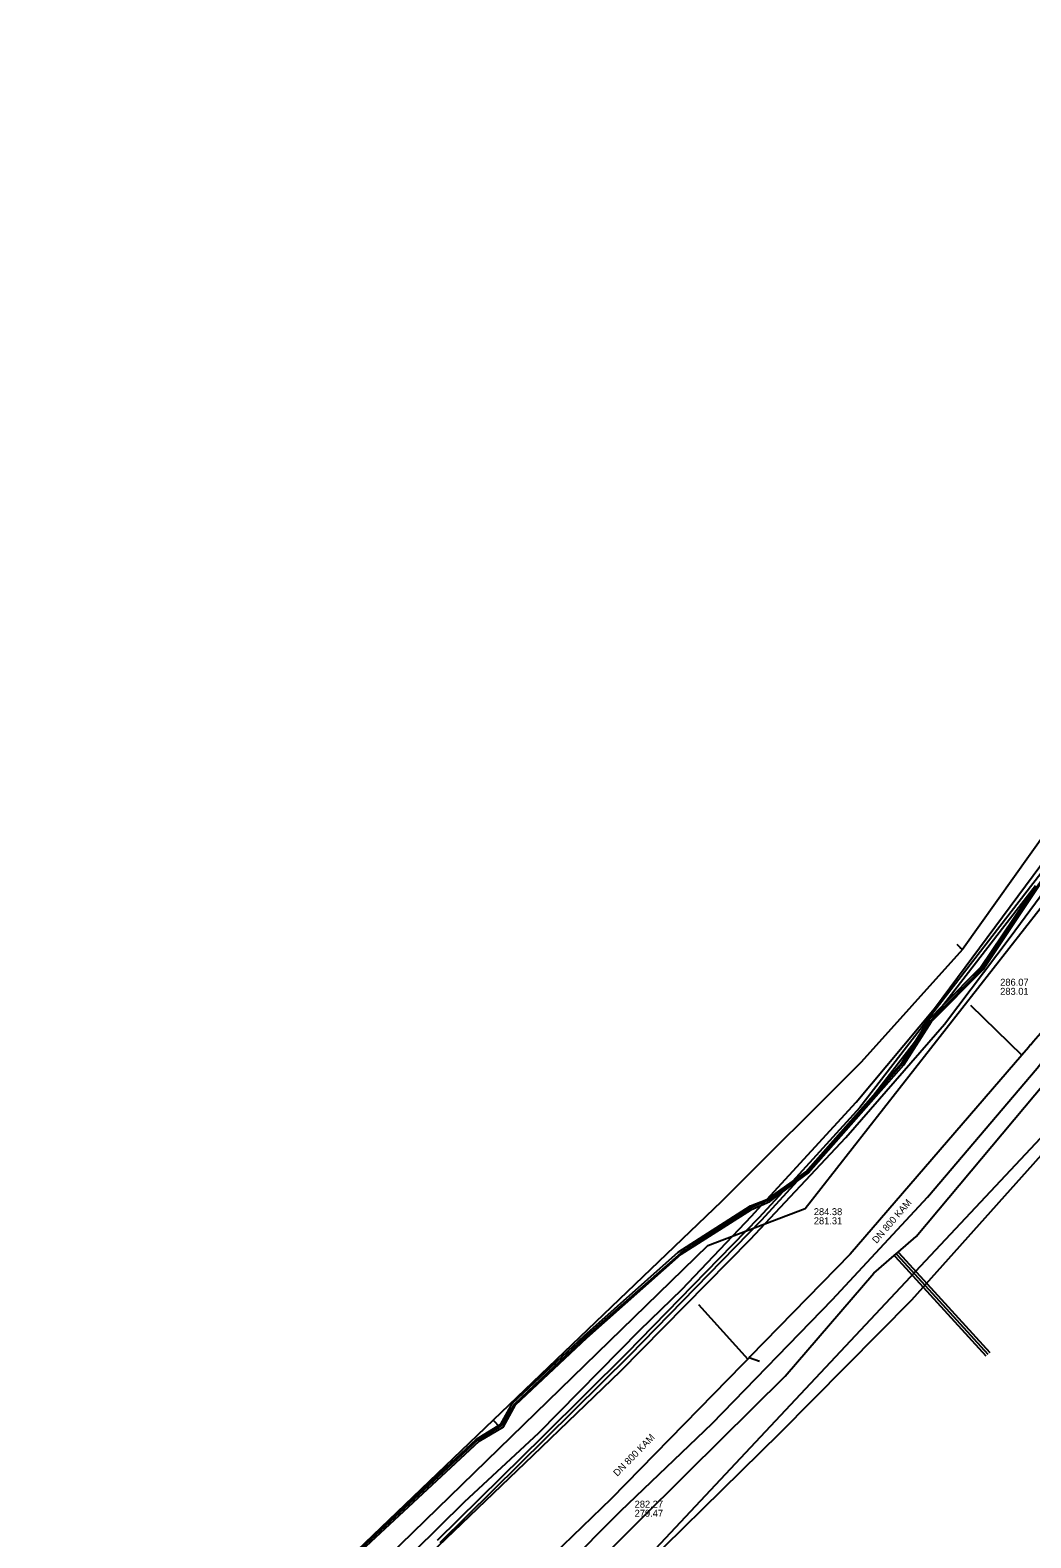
# Model space of a CAD drawing. Extents: x -598233 to -596890, y -1157848 to -1156431.
# Drawn here: x -597113.1 to -596997.9, y -1156997.4 to -1156824 of the extents above; entities that cross this region are included whole.
import ezdxf

# ---------------------------------------------------------------- set-up
doc = ezdxf.new("R2010")
doc.units = 0
for name, color, linetype in [('Vrstva 12', 7, 'Continuous'), ('Vrstva 13', 7, 'Continuous'), ('Vrstva 19', 7, 'Continuous'), ('Vrstva 44', 7, 'Continuous'), ('Vrstva 55', 7, 'Continuous'), ('Vrstva 58', 7, 'Continuous'), ('Vrstva 9', 7, 'Continuous')]:
    doc.layers.add(name, color=color, linetype=linetype)

msp = doc.modelspace()

# ---------------------------------------------------------------- linework, layer by layer
at = {"layer": 'Vrstva 12'}
for points in [[(-597013.15, -1156964.56), (-597011.08, -1156962.78), (-596994.85, -1156943.41)], [(-597096.15, -1157046.37), (-597080.65, -1157032.41), (-597068.22, -1157020.09), (-597055.1, -1157007.53), (-597037.34, -1156989.94), (-597026.15, -1156978.85), (-597015.97, -1156966.98), (-597013.61, -1156964.95)], [(-597013.61, -1156964.95), (-597013.38, -1156964.76)], [(-597013.38, -1156964.76), (-597013.15, -1156964.56)], [(-597002.58, -1156976.15), (-597008.97, -1156969.14), (-597013.02, -1156964.71), (-597013.15, -1156964.56)]]:
    msp.add_lwpolyline(points, dxfattribs=at)
at = {"layer": 'Vrstva 13'}
for p, q in [((-597006, -1156929.52), (-597006.36, -1156929.2)), ((-597005.76, -1156929.74), (-597006, -1156929.52)), ((-597059.77, -1156983.91), (-597059.54, -1156984.14)), ((-597059.54, -1156984.14), (-597059.21, -1156984.48))]:
    msp.add_line(p, q, dxfattribs=at)
for points in [[(-596967.78, -1156864.53), (-596968.28, -1156866.45), (-596969.12, -1156869.63), (-596975.82, -1156881.68), (-596987.36, -1156902), (-596995.97, -1156916.01), (-597005.76, -1156929.74), (-597017.4, -1156942.73), (-597033.49, -1156958.74), (-597059.77, -1156983.91), (-597076.36, -1156999.81), (-597090.23, -1157012.97), (-597109.08, -1157030.59), (-597111.35, -1157034.13), (-597112.48, -1157035.47), (-597112.98, -1157036.09)], [(-597003.02, -1156976.55), (-597009.42, -1156969.53), (-597013.47, -1156965.1), (-597013.61, -1156964.95)], [(-597002.8, -1156976.35), (-597009.2, -1156969.34), (-597013.24, -1156964.91), (-597013.38, -1156964.76)]]:
    msp.add_lwpolyline(points, dxfattribs=at)
at = {"layer": 'Vrstva 19'}
msp.add_lwpolyline([(-597070.67, -1157028.24), (-597069.06, -1157026.66), (-597068.04, -1157025.67), (-597047.41, -1157005.47), (-596990.41, -1156944.69), (-596980.1, -1156930.5), (-596969.41, -1156912.52), (-596962.33, -1156901.94), (-596955.88, -1156890.47), (-596948.03, -1156875.88), (-596944.82, -1156870.73), (-596944.5, -1156869.71)], dxfattribs=at)
at = {"layer": 'Vrstva 44'}
for points in [[(-597074.66, -1157004.75), (-597063.06, -1156993.3), (-597054.52, -1156985.37), (-597042.87, -1156973.56), (-597038.02, -1156968.83), (-597030.03, -1156960.43), (-597028.88, -1156959.17), (-597028.54, -1156958.8), (-597028.27, -1156958.51), (-597018, -1156947.32), (-597008.96, -1156936.55), (-596993.33, -1156915.45), (-596979.36, -1156891.26), (-596973.04, -1156878.64), (-596966.53, -1156865.27), (-596961.1, -1156853.21), (-596958.95, -1156848.68), (-596955.64, -1156843.49), (-596947.56, -1156826.18), (-596941.41, -1156813.85)], [(-596993.84, -1156917.29), (-597017.56, -1156947.92), (-597025.33, -1156956.43), (-597025.84, -1156956.99), (-597026.44, -1156957.64), (-597029.17, -1156960.64), (-597044.38, -1156976.19), (-597054.02, -1156985.75), (-597066.19, -1156997.75)], [(-597076.54, -1157000.38), (-597061.39, -1156986.32), (-597058.58, -1156984.67), (-597057.18, -1156982.13), (-597048.99, -1156974.43), (-597038.12, -1156964.8), (-597030.02, -1156959.68), (-597028.88, -1156959.17), (-597027.93, -1156958.74), (-597026.44, -1156957.64), (-597024.78, -1156956.42), (-597023.48, -1156955.47), (-597012.51, -1156943.03), (-597009.32, -1156938.03), (-597003.37, -1156932.06), (-596994.69, -1156919.04)], [(-596995.59, -1156920.2), (-597003.51, -1156931.93), (-597009.05, -1156937.58), (-597009.45, -1156937.99), (-597009.9, -1156938.68), (-597012.64, -1156942.89), (-597017.02, -1156947.88), (-597018.09, -1156949.09), (-597023.61, -1156955.38), (-597024.25, -1156955.84), (-597025.84, -1156956.99), (-597028.05, -1156958.58), (-597028.54, -1156958.8), (-597030.07, -1156959.49), (-597038.16, -1156964.69), (-597049.11, -1156974.3), (-597057.32, -1156982.05), (-597058.79, -1156984.53), (-597061.56, -1156986.22), (-597076.71, -1157000.33)], [(-597076.79, -1157000.19), (-597061.68, -1156986.08), (-597058.89, -1156984.38), (-597057.54, -1156981.94), (-597049.3, -1156974.21), (-597038.49, -1156964.57), (-597030.13, -1156959.25), (-597028.27, -1156958.51), (-597028.18, -1156958.47), (-597025.33, -1156956.43), (-597023.78, -1156955.32), (-597015.71, -1156946.19), (-597012.73, -1156942.81), (-597011.14, -1156940.29), (-597009.59, -1156937.81), (-597007.93, -1156936.13), (-597003.68, -1156931.84), (-596997.33, -1156922.45)], [(-596997.33, -1156922.45), (-597007.93, -1156936.13), (-597009.05, -1156937.58), (-597009.9, -1156938.68), (-597011.14, -1156940.29), (-597015.71, -1156946.19), (-597017.02, -1156947.88), (-597017.26, -1156948.18), (-597018.09, -1156949.09), (-597024.25, -1156955.84), (-597024.78, -1156956.42), (-597028.88, -1156960.91), (-597044.09, -1156976.48), (-597053.74, -1156986.03), (-597065.91, -1156998.03)]]:
    msp.add_lwpolyline(points, dxfattribs=at)
at = {"layer": 'Vrstva 55'}
for points in [[(-597069.74, -1157001.91), (-597055.17, -1156987.92), (-597045.1, -1156978.26), (-597030.18, -1156963.14), (-597019.16, -1156951.4), (-597007.83, -1156938.34), (-597000.27, -1156928.35), (-596991.63, -1156916.64), (-596988.25, -1156910.28), (-596981.73, -1156899.08), (-596978.12, -1156892.58), (-596971.83, -1156880.35), (-596964.21, -1156865.06), (-596948.88, -1156874.21), (-596946.12, -1156870.53), (-596945.7, -1156867.33), (-596942.11, -1156860.7), (-596931.98, -1156866.05), (-596927.82, -1156861.81), (-596924.03, -1156860.35)], [(-597058.24, -1157007.55), (-597045.07, -1156994.34), (-597034.55, -1156984.29), (-597020.7, -1156970.03), (-597009.79, -1156958.24), (-596997.15, -1156943.42), (-596987.85, -1156931.37), (-596977.1, -1156914.45), (-596969.49, -1156901.48), (-596959.56, -1156881.26), (-596954.35, -1156871.52), (-596948.75, -1156874.87)]]:
    msp.add_lwpolyline(points, dxfattribs=at)
at = {"layer": 'Vrstva 58'}
for points in [[(-597115.64, -1157042.19), (-597035.06, -1156963.83), (-597023.86, -1156959.57), (-596991.41, -1156918.15), (-596951.34, -1156839.56), (-596924.93, -1156788.51), (-596911.05, -1156767.47), (-596898.61, -1156749.4), (-596890.46, -1156742.24)], [(-597086.88, -1157045.18), (-597086.58, -1157044.59), (-597066.89, -1157025.23), (-597051.01, -1157009.31), (-597046.7, -1157005.01), (-597026.73, -1156985.36), (-597011.58, -1156970.08), (-596991.8, -1156947.93), (-596989.15, -1156945.07), (-596988.35, -1156943.93), (-596988.21, -1156942.76), (-596974.88, -1156923.46), (-596956.71, -1156889.88), (-596946.89, -1156871.03), (-596942.11, -1156860.2), (-596941.85, -1156859.79), (-596941.53, -1156859.01), (-596934.53, -1156842.22), (-596932.96, -1156839.31), (-596920.95, -1156815.01), (-596913.39, -1156801.07), (-596903.8, -1156786.32), (-596893.16, -1156776.74), (-596890.46, -1156773.58)]]:
    msp.add_lwpolyline(points, dxfattribs=at)
at = {"layer": 'Vrstva 9'}
for p, q in [((-597004.83, -1156936.18), (-596998.92, -1156941.9)), ((-597036.12, -1156970.59), (-597030.46, -1156976.87)), ((-597029.12, -1156977.14), (-597030.31, -1156976.72))]:
    msp.add_line(p, q, dxfattribs=at)
for points in [[(-596995.7, -1156938.18), (-596997.56, -1156940.33), (-596997.9, -1156940.72), (-596997.95, -1156940.78), (-596998.06, -1156940.91), (-596998.16, -1156941.03), (-596998.92, -1156941.9), (-597018.67, -1156964.82)], [(-597018.67, -1156964.82), (-597030.17, -1156976.57), (-597030.21, -1156976.62), (-597030.31, -1156976.72), (-597030.46, -1156976.87), (-597031.04, -1156977.46), (-597031.07, -1156977.5), (-597046.19, -1156992.95)], [(-597046.19, -1156992.95), (-597058.43, -1157004.78), (-597061.77, -1157008.01), (-597062.42, -1157008.65), (-597062.79, -1157009), (-597063.1, -1157009.3), (-597065.67, -1157011.79), (-597065.86, -1157011.97)]]:
    msp.add_lwpolyline(points, dxfattribs=at)

# ---------------------------------------------------------------- texts
at = {"layer": 'Vrstva 12'}
for s, p in [('286.07', (-597001.41, -1156933.92)), ('283.01', (-597001.41, -1156934.97)), ('284.38', (-597022.86, -1156960.32)), ('281.31', (-597022.86, -1156961.37)), ('282.27', (-597043.48, -1156993.97)), ('279.47', (-597043.48, -1156995.02))]:
    msp.add_text(s, height=0.8, dxfattribs=at).set_placement(p)
for rotation, p in [(49.2171, (-597015.63, -1156963.64)), (45.6647, (-597045.46, -1156990.43))]:
    msp.add_text('DN 800 KAM', height=0.8, rotation=rotation, dxfattribs=at).set_placement(p)

doc.saveas('drawing.dxf')
